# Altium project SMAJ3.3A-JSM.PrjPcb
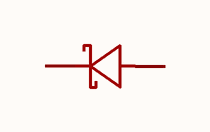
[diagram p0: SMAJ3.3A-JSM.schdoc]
1 sheet, 1 parts. Net scope: global (net labels, ports and power ports of the same name join across sheets).

## Sheet SMAJ3.3A-JSM.schdoc
size 127 x 101 mm

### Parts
D?  smaj3.3a-jsm  [SMA_L4.4-W2.6-LS5.0-RD]  (value not drawn)

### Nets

Not connected (* = marked no-connect by the designer): D? 1(K) 2(A)

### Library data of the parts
D? = smaj3.3a-jsm: 极性:单向;反向截止电压(Vrwm):3.3V;钳位电压:8V;峰值脉冲电流(Ipp):50A;峰值脉冲功率(Ppp):400W;击穿电压(VBR):6.5V;; Manufacturer: JSMSEMI(杰盛微); AddInBom: yes; ModelId: a2d22152f8d5421c8e96dbd56af7c345; ModelTransform: 204.724,98.425,0,0,0,0,0,0,0; Polarity: 单向; Reverse Stand-Off Voltage (Vrwm): 3.3V; Clamping Voltage: 8V; Peak Pulse Current (Ipp): 50A; Peak Pulse Power Dissipation (Ppp): 400W; Voltage - Breakdown: 6.5V; Reverse Leakage Current (Ir): 600uA; Number of Channels: 单路; Type: TVS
